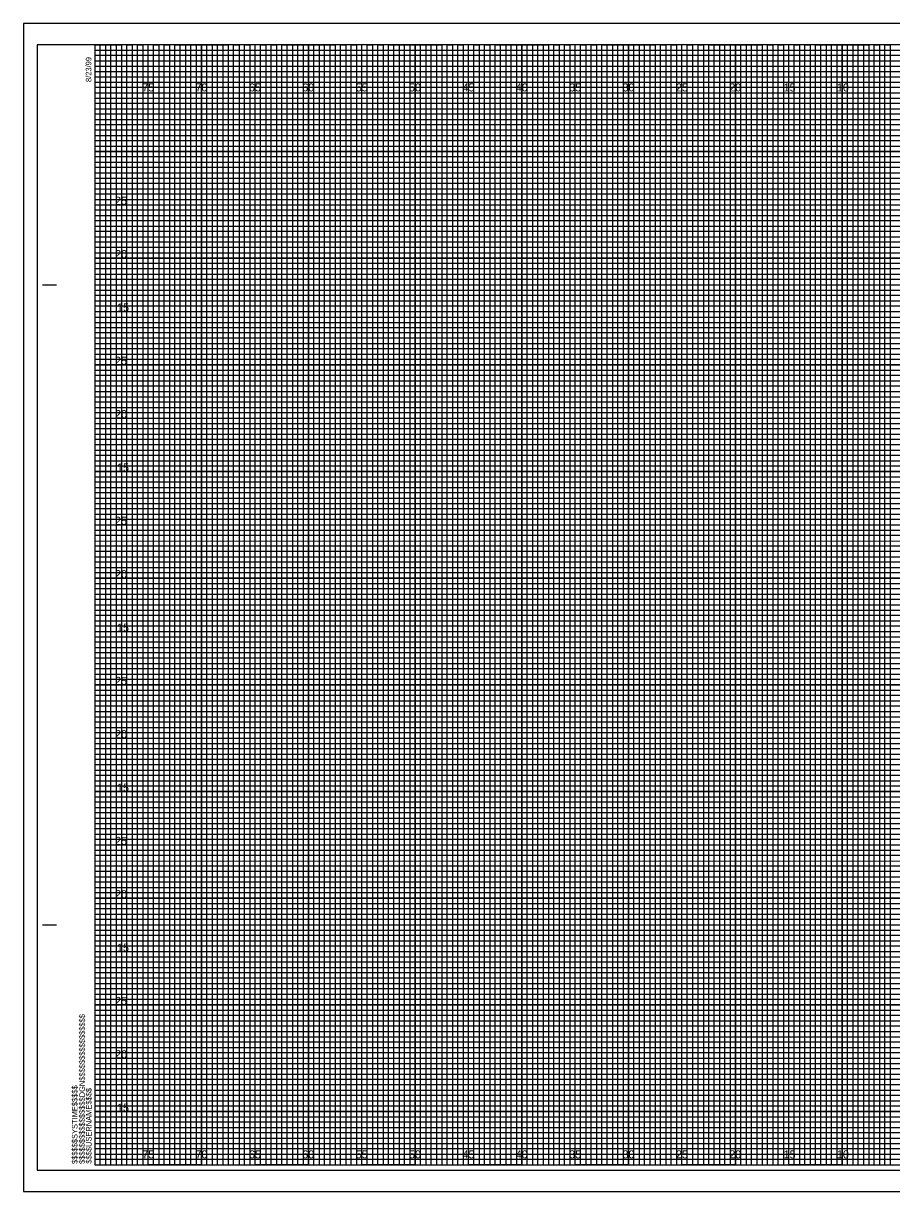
# Model space of a CAD drawing. Extents: x -7 to 162, y -3 to 107.
# Drawn here: x -6.7 to 74.6, y -2.5 to 107 of the extents above; entities that cross this region are included whole.
import ezdxf

# ---------------------------------------------------------------- set-up
doc = ezdxf.new("R2010")
doc.units = 0
for name, color, linetype in [('Exist Cross Section Cell', 7, 'Continuous'), ('Exist XS Center Line Elevation Label', 7, 'Continuous'), ('Exist XS Ground Line', 7, 'Continuous'), ('Prop CMT Pvmt Course 2', 7, 'Continuous'), ('Prop CMT Pvmt Course 3', 7, 'Continuous'), ('Prop CMT Pvmt Surface', 7, 'Continuous'), ('Prop CMT Pvmt Surface Shoulder', 7, 'Continuous'), ('Prop CMT Shld Paved Course 1', 7, 'Continuous'), ('Prop CMT Shld Paved Course 2', 7, 'Continuous'), ('Prop CMT Subgrade Earthwork', 7, 'Continuous'), ('Scratch_Level_0', 7, 'Continuous')]:
    doc.layers.add(name, color=color, linetype=linetype)

msp = doc.modelspace()

# ---------------------------------------------------------------- linework, layer by layer
at = {"layer": 'Exist XS Center Line Elevation Label'}
for points in [[(0, 105), (2.5, 105), (2.5, 0), (7.5, 0), (7.5, 105), (12.5, 105), (12.5, 0), (17.5, 0), (17.5, 105), (22.5, 105), (22.5, 0), (27.5, 0), (27.5, 105), (32.5, 105), (32.5, 0), (37.5, 0), (37.5, 105), (42.5, 105), (42.5, 0), (47.5, 0), (47.5, 105), (52.5, 105), (52.5, 0), (57.5, 0), (57.5, 105), (62.5, 105), (62.5, 0), (67.5, 0), (67.5, 105), (72.5, 105), (72.5, 0), (77.5, 0)], [(0, 102.5), (137.5, 102.5)], [(0, 92.5), (160, 92.5), (160, 97.5), (0, 97.5)], [(0, 82.5), (160, 82.5), (160, 87.5), (0, 87.5)], [(0, 72.5), (160, 72.5), (160, 77.5), (0, 77.5)], [(0, 62.5), (160, 62.5), (160, 67.5), (0, 67.5)], [(0, 52.5), (160, 52.5), (160, 57.5), (0, 57.5)], [(0, 42.5), (160, 42.5), (160, 47.5), (0, 47.5)], [(0, 32.5), (160, 32.5), (160, 37.5), (0, 37.5)], [(0, 22.5), (160, 22.5), (160, 27.5), (0, 27.5)], [(0, 12.5), (160, 12.5), (160, 17.5), (0, 17.5)], [(0, 2.5), (160, 2.5), (160, 7.5), (0, 7.5)]]:
    msp.add_lwpolyline(points, dxfattribs=at)
at = {"layer": 'Exist XS Ground Line'}
for p, q in [((5, 105), (0, 105)), ((5, 0), (5, 105)), ((15, 105), (10, 105)), ((10, 105), (10, 0)), ((15, 0), (15, 105)), ((25, 105), (20, 105)), ((20, 105), (20, 0)), ((25, 0), (25, 105)), ((35, 105), (30, 105)), ((30, 105), (30, 0)), ((35, 0), (35, 105)), ((45, 105), (40, 105)), ((40, 105), (40, 0)), ((45, 0), (45, 105)), ((55, 105), (50, 105)), ((50, 105), (50, 0)), ((55, 0), (55, 105)), ((65, 105), (60, 105)), ((60, 105), (60, 0)), ((65, 0), (65, 105)), ((75, 105), (70, 105)), ((70, 105), (70, 0)), ((10, 0), (5, 0)), ((20, 0), (15, 0)), ((30, 0), (25, 0)), ((40, 0), (35, 0)), ((50, 0), (45, 0)), ((60, 0), (55, 0)), ((70, 0), (65, 0))]:
    msp.add_line(p, q, dxfattribs=at)
for points in [[(0, 100), (160, 100), (160, 95), (0, 95)], [(0, 90), (160, 90), (160, 85), (0, 85)], [(0, 80), (160, 80), (160, 75), (0, 75)], [(0, 70), (160, 70), (160, 65), (0, 65)], [(0, 60), (160, 60), (160, 55), (0, 55)], [(0, 50), (160, 50), (160, 45), (0, 45)], [(0, 40), (160, 40), (160, 35), (0, 35)], [(0, 30), (160, 30), (160, 25), (0, 25)], [(0, 20), (160, 20), (160, 15), (0, 15)], [(0, 10), (160, 10), (160, 5), (0, 5)]]:
    msp.add_lwpolyline(points, dxfattribs=at)
at = {"layer": 'Prop CMT Pvmt Course 2'}
msp.add_lwpolyline([(-6.7, -2.5), (161.65, -2.5), (161.65, 107), (-6.7, 107)], close=True, dxfattribs=at)
at = {"layer": 'Prop CMT Pvmt Course 3'}
msp.add_lwpolyline([(-5.4, -0.5), (161.2, -0.5), (161.2, 105), (-5.4, 105)], close=True, dxfattribs=at)
at = {"layer": 'Prop CMT Pvmt Surface'}
for p, q in [((161.65, 107), (-6.7, 107)), ((-6.7, 107), (-6.7, -2.5)), ((-6.7, -2.5), (161.65, -2.5))]:
    msp.add_line(p, q, dxfattribs=at)
at = {"layer": 'Prop CMT Shld Paved Course 1'}
for p, q in [((-4.9, 82.5), (-3.65, 82.5)), ((-4.85, 82.5), (-3.6, 82.5)), ((-4.9, 22.5), (-3.65, 22.5)), ((-4.85, 22.5), (-3.6, 22.5)), ((0, 0), (0, 0)), ((0, 0), (0, 0)), ((0, 0), (0, 0)), ((0, 0), (0, 0)), ((0, 0), (0, 0)), ((0, 0), (0, 0)), ((0, 0), (0, 0))]:
    msp.add_line(p, q, dxfattribs=at)
msp.add_lwpolyline([(160, 105), (0, 105), (0, 0), (160, 0)], close=True, dxfattribs=at)
at = {"layer": 'Prop CMT Shld Paved Course 2'}
for points in [[(0, 0), (0.5, 0), (0.5, 105), (1, 105), (1, 0)], [(1, 0), (1.5, 0), (1.5, 105), (2, 105), (2, 0)], [(2.5, 0), (3, 0), (3, 105), (3.5, 105), (3.5, 0)], [(3.5, 0), (4, 0), (4, 105), (4.5, 105), (4.5, 0)], [(5, 0), (5.5, 0), (5.5, 105), (6, 105), (6, 0)], [(6, 0), (6.5, 0), (6.5, 105), (7, 105), (7, 0)], [(7.5, 0), (8, 0), (8, 105), (8.5, 105), (8.5, 0)], [(8.5, 0), (9, 0), (9, 105), (9.5, 105), (9.5, 0)], [(10, 0), (10.5, 0), (10.5, 105), (11, 105), (11, 0)], [(11, 0), (11.5, 0), (11.5, 105), (12, 105), (12, 0)], [(12.5, 0), (13, 0), (13, 105), (13.5, 105), (13.5, 0)], [(13.5, 0), (14, 0), (14, 105), (14.5, 105), (14.5, 0)], [(15, 0), (15.5, 0), (15.5, 105), (16, 105), (16, 0)], [(16, 0), (16.5, 0), (16.5, 105), (17, 105), (17, 0)], [(17.5, 0), (18, 0), (18, 105), (18.5, 105), (18.5, 0)], [(18.5, 0), (19, 0), (19, 105), (19.5, 105), (19.5, 0)], [(20, 0), (20.5, 0), (20.5, 105), (21, 105), (21, 0)], [(21, 0), (21.5, 0), (21.5, 105), (22, 105), (22, 0)], [(22.5, 0), (23, 0), (23, 105), (23.5, 105), (23.5, 0)], [(23.5, 0), (24, 0), (24, 105), (24.5, 105), (24.5, 0)], [(25, 0), (25.5, 0), (25.5, 105), (26, 105), (26, 0)], [(26, 0), (26.5, 0), (26.5, 105), (27, 105), (27, 0)], [(27.5, 0), (28, 0), (28, 105), (28.5, 105), (28.5, 0)], [(28.5, 0), (29, 0), (29, 105), (29.5, 105), (29.5, 0)], [(30, 0), (30.5, 0), (30.5, 105), (31, 105), (31, 0)], [(31, 0), (31.5, 0), (31.5, 105), (32, 105), (32, 0)], [(32.5, 0), (33, 0), (33, 105), (33.5, 105), (33.5, 0)], [(33.5, 0), (34, 0), (34, 105), (34.5, 105), (34.5, 0)], [(35, 0), (35.5, 0), (35.5, 105), (36, 105), (36, 0)], [(36, 0), (36.5, 0), (36.5, 105), (37, 105), (37, 0)], [(37.5, 0), (38, 0), (38, 105), (38.5, 105), (38.5, 0)], [(38.5, 0), (39, 0), (39, 105), (39.5, 105), (39.5, 0)], [(40, 0), (40.5, 0), (40.5, 105), (41, 105), (41, 0)], [(41, 0), (41.5, 0), (41.5, 105), (42, 105), (42, 0)], [(42.5, 0), (43, 0), (43, 105), (43.5, 105), (43.5, 0)], [(43.5, 0), (44, 0), (44, 105), (44.5, 105), (44.5, 0)], [(45, 0), (45.5, 0), (45.5, 105), (46, 105), (46, 0)], [(46, 0), (46.5, 0), (46.5, 105), (47, 105), (47, 0)], [(47.5, 0), (48, 0), (48, 105), (48.5, 105), (48.5, 0)], [(48.5, 0), (49, 0), (49, 105), (49.5, 105), (49.5, 0)], [(50, 0), (50.5, 0), (50.5, 105), (51, 105), (51, 0)], [(51, 0), (51.5, 0), (51.5, 105), (52, 105), (52, 0)], [(52.5, 0), (53, 0), (53, 105), (53.5, 105), (53.5, 0)], [(53.5, 0), (54, 0), (54, 105), (54.5, 105), (54.5, 0)], [(55, 0), (55.5, 0), (55.5, 105), (56, 105), (56, 0)], [(56, 0), (56.5, 0), (56.5, 105), (57, 105), (57, 0)], [(57.5, 0), (58, 0), (58, 105), (58.5, 105), (58.5, 0)], [(58.5, 0), (59, 0), (59, 105), (59.5, 105), (59.5, 0)], [(60, 0), (60.5, 0), (60.5, 105), (61, 105), (61, 0)], [(61, 0), (61.5, 0), (61.5, 105), (62, 105), (62, 0)], [(62.5, 0), (63, 0), (63, 105), (63.5, 105), (63.5, 0)], [(63.5, 0), (64, 0), (64, 105), (64.5, 105), (64.5, 0)], [(65, 0), (65.5, 0), (65.5, 105), (66, 105), (66, 0)], [(66, 0), (66.5, 0), (66.5, 105), (67, 105), (67, 0)], [(67.5, 0), (68, 0), (68, 105), (68.5, 105), (68.5, 0)], [(68.5, 0), (69, 0), (69, 105), (69.5, 105), (69.5, 0)], [(70, 0), (70.5, 0), (70.5, 105), (71, 105), (71, 0)], [(71, 0), (71.5, 0), (71.5, 105), (72, 105), (72, 0)], [(72.5, 0), (73, 0), (73, 105), (73.5, 105), (73.5, 0)], [(73.5, 0), (74, 0), (74, 105), (74.5, 105), (74.5, 0)]]:
    msp.add_lwpolyline(points, dxfattribs=at)
at = {"layer": 'Prop CMT Subgrade Earthwork'}
for p, q in [((5, 0), (5, 105)), ((10, 0), (10, 105)), ((15, 0), (15, 105)), ((20, 0), (20, 105)), ((25, 0), (25, 105)), ((30, 0), (30, 105)), ((35, 0), (35, 105)), ((40, 0), (40, 105)), ((45, 0), (45, 105)), ((50, 0), (50, 105)), ((55, 0), (55, 105)), ((60, 0), (60, 105)), ((65, 0), (65, 105)), ((70, 0), (70, 105)), ((0, 100), (160, 100)), ((0, 95), (160, 95)), ((0, 90), (160, 90)), ((0, 85), (160, 85)), ((0, 80), (160, 80)), ((0, 75), (160, 75)), ((0, 70), (160, 70)), ((0, 65), (160, 65)), ((0, 60), (160, 60)), ((0, 55), (160, 55)), ((0, 50), (160, 50)), ((0, 45), (160, 45)), ((0, 40), (160, 40)), ((0, 35), (160, 35)), ((0, 30), (160, 30)), ((0, 25), (160, 25)), ((0, 20), (160, 20)), ((0, 15), (160, 15)), ((0, 10), (160, 10)), ((0, 5), (160, 5))]:
    msp.add_line(p, q, dxfattribs=at)
at = {"layer": 'Scratch_Level_0'}
for p, q in [((0, 104.5), (130, 104.5)), ((130, 103.99), (0, 103.99)), ((0, 103.99), (0, 103.5)), ((0, 103.5), (130, 103.5)), ((130, 102.95), (0, 102.95)), ((0, 102.95), (0, 102)), ((0, 102), (160, 102))]:
    msp.add_line(p, q, dxfattribs=at)
for points in [[(0, 101.5), (135, 101.5), (160, 101.5), (160, 101), (0, 101)], [(0, 100.5), (160, 100.5), (160, 99.5), (0, 99.5)], [(0, 99), (160, 99), (160, 98.5), (0, 98.49)], [(0, 98), (160, 98), (160, 97), (0, 97)], [(0, 96.5), (160, 96.5), (160, 96), (0, 96)], [(0, 95.5), (160, 95.5), (160, 94.5), (0, 94.5)], [(0, 94), (160, 94), (160, 93.5), (0, 93.5)], [(0, 93), (160, 93), (160, 92), (0, 92)], [(0, 91.5), (160, 91.5), (160, 91), (0, 91)], [(0, 90.5), (160, 90.5), (160, 89.5), (0, 89.5)], [(0, 89), (160, 89), (160, 88.5), (0, 88.5)], [(0, 88), (160, 88), (160, 86.98), (160, 86.5), (160, 86), (0, 86)], [(0, 87), (160, 87), (160, 86.5), (0, 86.5)], [(0, 85.5), (160, 85.5), (160, 84.5), (0, 84.52)], [(0, 84.52), (160, 84.5), (160, 84), (0, 84)], [(0, 83.5), (160, 83.5), (160, 83), (0, 83)], [(0, 82), (160, 82), (160, 81.5), (0, 81.5)], [(0, 81), (160, 81), (160, 80.5), (0, 80.5)], [(-0.04, 79.45), (160, 79.45), (160, 78.94), (-0.04, 78.94)], [(0, 78.5), (160, 78.5), (160, 78), (0, 78)], [(0, 77), (160, 77), (160, 76.5), (0, 76.5)], [(0, 76), (160, 76), (160, 75.5), (0, 75.5)], [(0, 74.5), (160, 74.5), (160, 74), (0, 74)], [(0, 73.5), (160, 73.5), (160, 73), (0, 73)], [(0, 72), (160, 72), (160, 71.5), (0, 71.5)], [(0, 71), (160, 71), (160, 70.5), (0, 70.5)], [(0, 69.5), (160, 69.5), (160, 68.99), (0, 69)], [(0, 68.5), (160, 68.5), (160, 68), (0, 68)], [(0, 67), (160, 67), (160, 66.5), (0, 66.5)], [(0, 66), (160, 66), (160, 65.5), (0, 65.5)], [(0, 64.5), (160, 64.5), (160, 64), (0, 64)], [(0, 63.5), (160, 63.5), (160, 63), (0, 63)], [(0, 62), (160, 62), (160, 61.5), (0, 61.5)], [(0, 61), (160, 61), (160, 60.5), (0, 60.5)], [(0, 59.5), (160, 59.5), (160, 59), (0, 59)], [(0, 58.5), (160.03, 58.45), (160, 58), (0, 58)], [(0, 57), (160, 57), (160, 56.5), (0, 56.5)], [(0, 56), (160, 56), (160, 55.5), (0, 55.5)], [(0, 54.5), (160, 54.5), (160, 54), (0, 54)], [(0, 53.5), (160, 53.5), (160, 53), (0, 53)], [(0, 52), (160, 52), (160, 51.5), (0, 51.5)], [(0, 51), (160, 51), (160, 50.5), (0, 50.5)], [(0, 49.5), (160, 49.5), (160, 49), (0, 49)], [(0, 48.5), (160, 48.5), (160, 48), (0, 48)], [(0, 47), (160, 47), (160, 46.5), (0, 46.5)], [(0, 46), (160, 46), (160, 45.5), (0, 45.5)], [(0, 44.5), (160, 44.5), (160, 44), (0, 44)], [(0, 43.5), (160, 43.5), (160, 43), (0, 43)], [(0, 42), (160, 42), (160, 41.5), (0, 41.5)], [(0, 41), (160, 41), (160, 40.5), (0, 40.5)], [(0, 39.5), (160, 39.5), (160, 38.99), (0, 39)], [(0, 38.5), (160, 38.5), (160, 38), (0, 38)], [(0, 37), (160, 37), (160, 36.5), (0, 36.5)], [(0, 36), (160, 36), (160, 35.5), (0, 35.5)], [(0, 34.5), (160, 34.5), (160, 34), (0, 34)], [(0, 33.5), (160, 33.5), (160, 33), (0, 33)], [(0, 32), (160, 32), (160, 31.5), (0, 31.5)], [(0, 31), (160, 31), (160, 30.5), (0, 30.5)], [(0, 29.5), (160, 29.5), (160, 29), (0, 29)], [(0, 28.5), (160.03, 28.46), (160, 28), (0, 28)], [(0, 27), (160, 27), (160, 26.5), (0, 26.5)], [(0, 26), (160, 26), (160, 25.5), (0, 25.5)], [(0, 24.5), (160, 24.5), (160, 24), (0, 24)], [(0, 23.5), (160, 23.5), (160, 23), (0, 23)], [(0, 22), (160, 22), (160, 21.5), (0, 21.5)], [(0, 21), (160, 21), (160, 20.5), (0, 20.5)], [(0, 19.5), (160, 19.5), (160, 19), (0, 19)], [(0, 18.5), (160, 18.5), (160, 18), (0, 18)], [(0, 17), (160, 17), (160, 16.5), (0, 16.5)], [(0, 16), (160, 16), (160, 15.5), (0, 15.5)], [(0, 14.5), (160, 14.5), (160, 14), (0, 14)], [(0, 13.5), (160, 13.5), (160, 13), (0, 13)], [(0, 12), (160, 12), (160, 11.5), (0, 11.5)], [(0, 11), (160, 11), (160, 10.5), (0, 10.5)], [(0, 9.5), (160, 9.5), (160, 9), (0, 9)], [(0, 8.5), (160, 8.5), (160, 8), (0, 8)], [(0, 7), (160, 7), (160, 6.5), (0, 6.5)], [(0, 6), (160, 6), (160, 5.5), (0, 5.5)], [(0, 4.5), (160, 4.5), (160, 4), (0, 4)], [(0, 3.5), (160, 3.5), (160, 3), (0, 3)], [(0, 2), (160, 2), (160, 1.5), (0, 1.5)], [(0, 1), (160, 1), (160, 0.5), (0, 0.5)]]:
    msp.add_lwpolyline(points, dxfattribs=at)

# ---------------------------------------------------------------- texts
at = {"layer": 'Exist Cross Section Cell'}
for s, p in [('75', (4.44, 100.62)), ('70', (9.43, 100.62)), ('65', (14.44, 100.62)), ('60', (19.43, 100.62)), ('55', (24.44, 100.62)), ('50', (29.43, 100.62)), ('45', (34.44, 100.62)), ('40', (39.43, 100.62)), ('35', (44.44, 100.62)), ('30', (49.43, 100.62)), ('25', (54.44, 100.62)), ('20', (59.43, 100.62)), ('15', (64.53, 100.62)), ('10', (69.52, 100.62)), ('75', (4.44, 0.62)), ('70', (9.43, 0.62)), ('65', (14.44, 0.62)), ('60', (19.43, 0.62)), ('55', (24.44, 0.62)), ('50', (29.43, 0.62)), ('45', (34.44, 0.62)), ('40', (39.43, 0.62)), ('35', (44.44, 0.62)), ('30', (49.43, 0.62)), ('25', (54.44, 0.62)), ('20', (59.43, 0.62)), ('15', (64.53, 0.62)), ('10', (69.52, 0.62))]:
    msp.add_text(s, height=0.75, dxfattribs=at).set_placement(p)
at = {"layer": 'Prop CMT Pvmt Surface Shoulder'}
for s, p in [('25', (1.89, 90)), ('20', (1.9, 85)), ('15', (2.08, 80)), ('25', (1.89, 75)), ('20', (1.9, 70)), ('15', (2.08, 65)), ('25', (1.89, 60)), ('20', (1.9, 55)), ('15', (2.08, 50)), ('25', (1.89, 45)), ('20', (1.9, 40)), ('15', (2.08, 35)), ('25', (1.89, 30)), ('20', (1.9, 25)), ('15', (2.08, 20)), ('25', (1.89, 15)), ('20', (1.9, 10)), ('15', (2.08, 5))]:
    msp.add_text(s, height=0.75, dxfattribs=at).set_placement(p)
at = {"layer": 'Prop CMT Shld Paved Course 1'}
for s, p in [('8/23/99', (-0.33, 101.5)), ('$$$$$$$$$$$$$$$$DGN$$$$$$$$$$$$$$$$', (-0.94, 0.09)), ('$$$$$$SYSTIME$$$$$', (-1.63, 0.09)), ('$$$$USERNAME$$$$', (-0.31, 0.12))]:
    msp.add_text(s, height=0.525, rotation=90, dxfattribs=at).set_placement(p)

doc.saveas('drawing.dxf')
